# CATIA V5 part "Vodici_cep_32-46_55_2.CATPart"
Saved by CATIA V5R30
Part number: Vodici_cep_32-46_55_2
Definition: E 1000_32-46_55
Nomenclature: E 1000_32-46_55
Source: Unknown
Description: PART--DESC
Bounding box of the stored display mesh (mm): x 163.7 to 210.3, y 113.7 to 160.3, z -101 to 9
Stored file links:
  E:\Bakalarka\Model\Forma_v7\Vodici_cep_32-46_55_2.CATPart
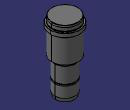
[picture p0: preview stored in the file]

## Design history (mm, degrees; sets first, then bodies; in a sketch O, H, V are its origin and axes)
Body1 "MANIFOLD_SOLID_BREP #3962" (main body)
  Solid1: solid without history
